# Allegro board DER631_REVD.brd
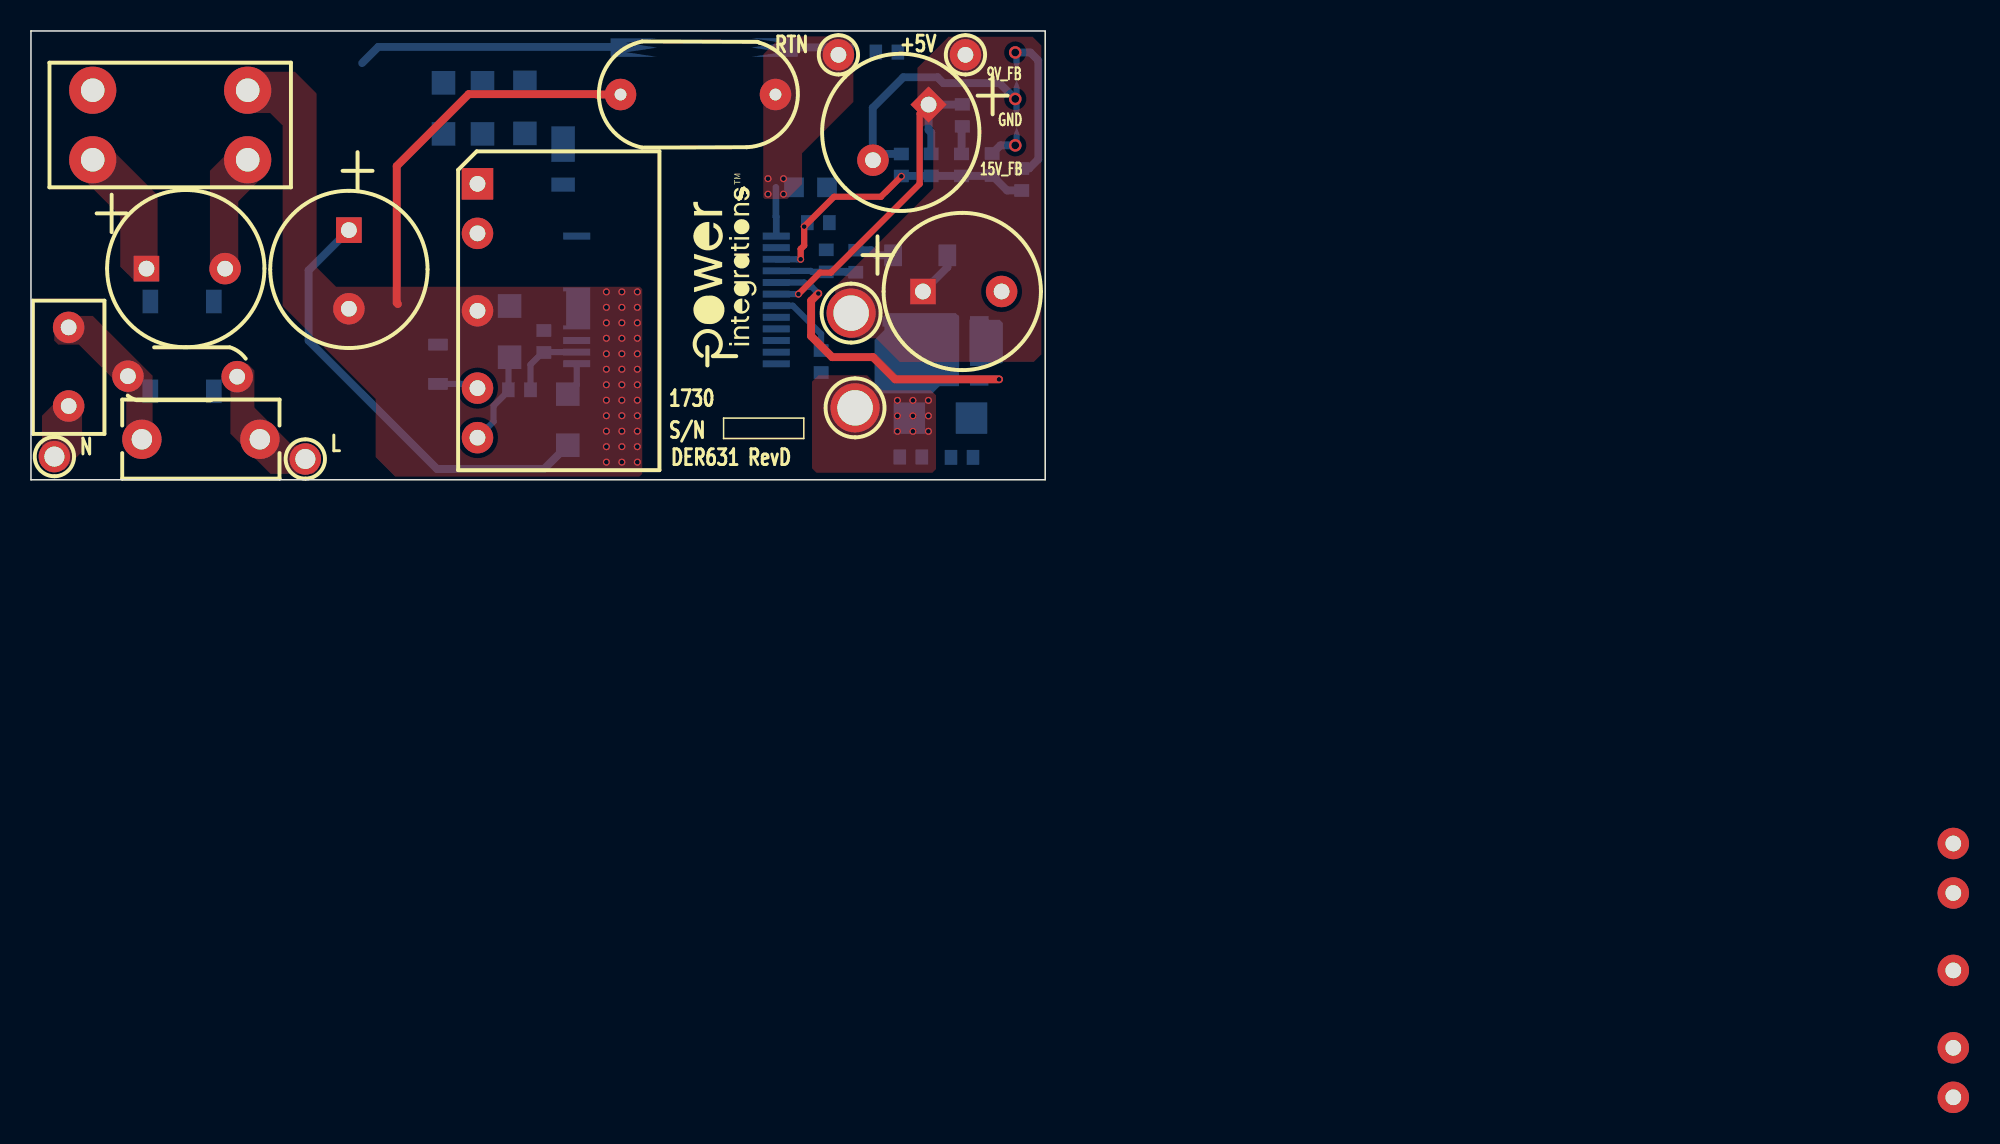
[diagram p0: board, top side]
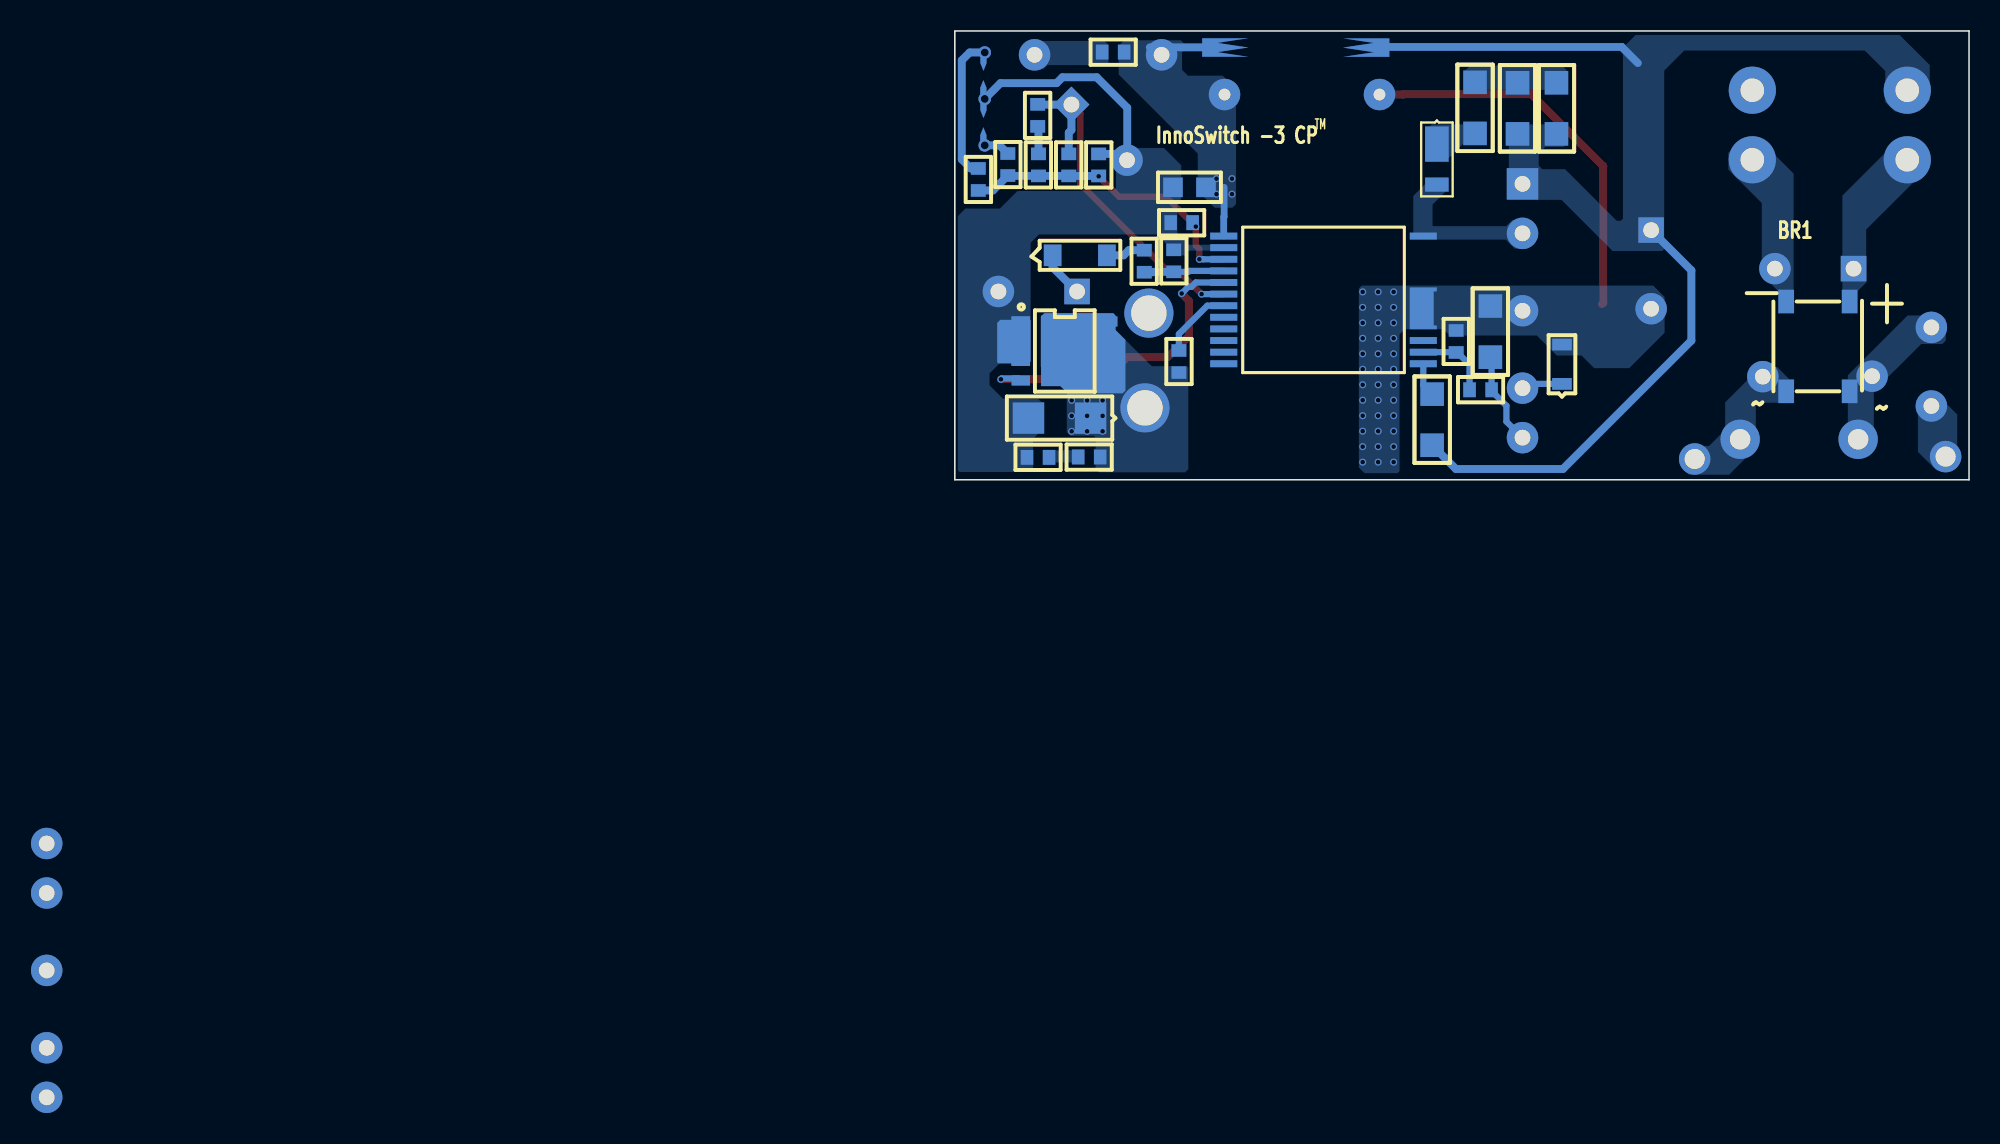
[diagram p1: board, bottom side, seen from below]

Outline 65.5 x 29 mm; copper layers: TOP, BOTTOM. Coordinates in mm from the lower left corner of the outline.
Outline path: 0,29 65.5,29 65.5,0 0,0 0,29

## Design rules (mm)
constraint set DEFAULT: min track width 0.508

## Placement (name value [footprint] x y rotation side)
BR1  Z4GP206L  [PI_SM_D_Z4]  7.72 11.53 180 bottom
C1  47 nF  [PI_NP395X200LS300D040]  14.78 2.62 180 top
C3  27 uF  [PIPOLCAPCYLD400LS200040]  20.53 16.13 270 top
C5  0.47 uF  [PISMC0603]  33.12 8.23 90 bottom
C6  22 uf  [PISMC1206]  30.91 7.92 90 bottom
C7  2.2 nF  [PINPCAPRAD374X275LS394D030]  38.07 24.89 0 top
C8  470 pF  [PISMC0603]  59.41 1.45 0 bottom
C9  2.2 uF  [PISMC0603]  51.36 13.44 90 bottom
C11  330 pF  [PISMC0603]  51.56 16.61 180 bottom
C12  4.7 nF  [PISMC0603]  60.1 21.06 270 bottom
C13  1 uF  [PISMC0603]  55.98 27.64 180 bottom
C14  560 uF  [PIPOLCAPCYLD400LS200040]  57.97 24.24 225 top
C15  560 uF  [PIPOLCAPCYLD400LS200040]  57.6 12.17 0 top
C17  27 uF  [PIPOLCAPCYLD400LS200040]  7.46 13.64 0 top
C18  470 pF  [PISMC1206]  26.64 22.35 90 bottom
D1  DFLR1600  [PISMDDFLR120012]  34.37 21.71 90 bottom
D2  BAV21WS-7-F  [PISMSOD323]  26.29 6.2 90 bottom
D4  STPS2H100AY  [PISMDSMA]  56.73 3.99 0 bottom
F1  1 A  [PI_RST_MICROFUSE]  2.43 4.77 90 top
FL1  Hole_90  [PI_HOLE_70MIL]  52.97 10.74 0 top
FL2  Hole_90  [PI_HOLE_70MIL]  53.22 4.62 0 top
L1  10 mH  [PI_IND_4P_590X295LS394X177D060]  13.97 20.7 0 top
NOREF  -  []  42.98 7.34 90 top
NOREF#2  -  []  0 29 0 top
NOREF#3  -  []  65.5 0 90 top
NOREF#4  -  []  -150.78 54.23 0 top
NOREF#5  -  []  -228.6 -144.78 0 top
Q3  BSC028N06LS3GATMA1  [PI_SM_PG-TDSON-8]  61.24 10.23 270 bottom
R5  51  [PISMR1206]  31.9 25.68 270 bottom
R8  10 k  [PISMR0603]  30.83 5.82 0 bottom
R10  47  [PISMR0603]  51.03 6.93 90 bottom
R13  4.7  [PISMR0603]  57.53 1.47 180 bottom
R14  100 k  [PISMR0603]  58.14 21.06 270 bottom
R15  33 K  [PISMR0603]  56.21 19.63 90 bottom
R16  0.005  [PISMR0805]  51.41 18.9 180 bottom
R19  2.2M  [PISMR1206]  34.67 2.23 90 bottom
R21  200 k  [PISMR1206]  29.16 22.35 90 bottom
R22  32.4 k  [PISMR0603]  63.98 18.69 90 bottom
R23  12.4 k  [PISMR0603]  62.08 19.66 90 bottom
R24  0.0  [PISMR0603]  60.15 24.26 270 bottom
R25  1 k  [PISMR0603]  53.26 14.83 270 bottom
RV1  275 Vac  [PIDISC350X160LS210X140040]  13.32 6.66 210 top
T2  EQ20  [PI_BOBBIN_EQ20_10P_H]  34.09 10.92 0 top
TP1  L  [PITPKEYSTONE100X100]  17.72 1.34 0 top
TP2  N  [PITPKEYSTONE100X100]  1.51 1.5 0 top
TP10  RET  [PITPKEYSTONE100X100]  52.15 27.46 0 top
TP11  +5V  [PITPKEYSTONE100X100]  60.35 27.46 0 top
U1  INN3268C  [PI_IC_INSOP_24D]  48.13 15.75 180 bottom
VR1  MMSZ5245B  [PI_SM_SOD-123_12]  59.18 14.5 180 bottom

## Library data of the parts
BR1 = DISCRETE BRIDGE_+~~-
C1 C5-C9 C11-C13 C18 = CAP NP
C3 C17 = CAP POL: alternate symbols: (pipolcapclyd400x675ls200040h)
C14 C15 = CAP POL
D1 D2 = DIODE
D4 = DIODE SCHOTTKY
F1 = FUSE: alternate symbols: (pirstmicrofusehoz)
FL1 FL2 = FlyingLead
L1 = INDUCTOR_4P_revD
Q3 = FET_N_TSDSON-8
R5 R8 R10 R13-R16 R19 R21-R25 = R
RV1 = VARISTOR: alternate symbols: (pi_disc_354x220_ls220x10_040_h)
T2 = BEQ20_10P
TP1 TP2 TP10 TP11 = TESTPOINT
U1 = DEV_InSOP_0
VR1 = DIODE_ZENER

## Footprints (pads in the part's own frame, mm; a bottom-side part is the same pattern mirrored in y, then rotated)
PI_BOBBIN_EQ20_10P_H
  rect 2.032x2.032 hole 1.016: 1(-5.25,8.2)
  round 2.032 hole 1.016: 2(-5.25,5) 3(-5.25,0) 4(-5.25,-5) 5(-5.25,-8.2) 6(90.061,-50.821) 7(90.061,-47.621) 8(90.061,-42.621) 9(90.061,-37.621) 10(90.061,-34.421)
PI_HOLE_70MIL
  round 3.175 hole 2.286: 1(0,0.025)
PI_IC_INSOP_24D
  rect 1.75x0.45 smd: 1(0,0) 2(0,-0.75) 3(0,-1.5) 4(0,-2.25) 5(0,-3) 6(0,-3.75) 7(0,-4.5) 8(0,-5.25) 9(0,-6) 10(0,-6.75) 11(0,-7.5) 12(0,-8.25) 13(12.89,-8.25) 14(12.89,-7.5) 15(12.89,-6.75) 24(12.89,0)
  custom 0.438x0.438 smd: 16(12.89,-4.67)
PI_IND_4P_590X295LS394X177D060
  round 3.048 hole 1.524: 1(0.025,-0.025) 2(0.025,4.47) 3(-9.982,4.47) 4(-9.982,-0.025)
PI_NP395X200LS300D040
  round 2.54 hole 1.321: 1(0,0) 2(7.62,0)
PI_RST_MICROFUSE
  round 2.032 hole 1.016: 1(0,0) 2(5.08,0)
PI_SM_D_Z4
  rect 1.016x1.524 smd: 1(0.01,-0.01) 2(0.01,-5.81) 3(-4.09,-5.81) 4(-4.09,-0.01)
PI_SM_PG-TDSON-8
  rect 0.66x1.194 smd: 1(0,0) 2(1.27,0) 3(2.54,0) 4(3.81,0) 5(3.81,5.65) 6(2.54,5.65) 7(1.27,5.65) 8(0,5.65)
PI_SM_SOD-123_12
  rect 1.143x1.397 smd: 1(0,0) 2(3.505,0)
PIDISC350X160LS210X140040
  round 2.032 hole 1.016: 1(0,0) 2(6.096,-3.556)
PINPCAPRAD374X275LS394D030
  round 2.032 hole 0.762: 1(0,0) 2(10.008,0)
PIPOLCAPCYLD400LS200040
  rect 1.651x1.651 hole 1.016: 1(0,0)
  round 2.032 hole 1.016: 2(5.08,0)
PISMC0603
  rect 0.813x0.965 smd: 1(0,0) 2(1.422,0)
PISMC1206
  rect 1.524x1.524 smd: 1(0,0) 2(3.302,0)
PISMDDFLR120012
  rect 2.286x1.524 smd: 1(-0.025,0)
  rect 0.914x1.524 smd: 2(-2.642,0)
PISMDSMA
  rect 2.032x2.032 smd: 1(0,0) 2(4.013,0)
PISMR0603
  rect 0.813x0.965 smd: 1(0,0) 2(1.422,0)
PISMR0805
  rect 1.27x1.27 smd: 1(0,0) 2(2.134,0)
PISMR1206
  rect 1.524x1.524 smd: 1(0,0) 2(3.302,0)
PISMSOD323
  rect 0.762x1.27 smd: 1(0,0) 2(2.54,0)
PITPKEYSTONE100X100
  round 2.032 hole 1.295: 1(0,0)

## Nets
GND_POWER: C8.2 C9.2 C11.1 C14.2 C15.2 D4.2 Q3.1(S1) R15.2 R16.1 U1.2
GND_SIGNAL: C3.2 C5.2 C6.2 C7.1 D2.2 L1.2 T2.3 U1.16
D6: Q3.6
D7: Q3.7
D8: Q3.8
NC8: U1.8
NC9: U1.9
NC10: U1.10
NC11: U1.11
NC12: U1.12
NC15: U1.15
S2: Q3.2
S3: Q3.3
N11018979: C13.1 C14.1 C15.1 FL1.1 R14.1 R24.1 TP11.1 U1.6 VR1.1
N11018987: C7.2 C13.2 R16.2 TP10.1 U1.1
N11019023: R10.2 U1.7
N11019027: D4.1 FL2.1 Q3.5 R10.1 R13.2
N11019129: Q3.4 U1.5
N11019153: D1.1 R5.2
N11019263: BR1.4 C17.2 L1.1
N11019293: C5.1 R8.2 U1.14
N11019397: BR1.3(AC2) C1.1 RV1.1 TP1.1
N11019401: C8.1 R13.1
N11019569: C6.1 R8.1 T2.5
N11019593: R19.2 U1.13(VPIN)
N11019613: C3.1 C18.1 L1.3 R19.1 R21.1 T2.1
N11019673: BR1.2 C1.2 F1.2 RV1.2
N11019681: BR1.1 C17.1 L1.4
N11019743: C11.2 C12.2 R14.2 R15.1 R22.1 R23.1 U1.3
N11020702: C18.2 R5.1 R21.2
N11020753: D1.2 T2.2 U1.24
N11026403: F1.1 TP2.1
N11053934: D2.1 T2.4
N11096846: R22.2
N11102317: R23.2
N11111738: C12.1 R24.2
N11113310: C9.1 R25.2 U1.4
N11114484: R25.1 VR1.2

Pads without a net: T2 6 7 8 9 10

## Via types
v1: diameter 0.813, hole 0.508, TOP to BOTTOM, 3 vias
v2: diameter 0.457, hole 0.305, TOP to BOTTOM, 55 vias

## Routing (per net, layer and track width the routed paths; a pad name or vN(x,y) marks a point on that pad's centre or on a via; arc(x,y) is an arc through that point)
GND_POWER: length 16
  BOTTOM w0.508: v1(63.57,24.61) 62.55,25.63 58.93,25.63 58.55,26.01 56.34,26.01 54.37,24.04 54.37,20.64 54.78,21.05 R15.2
GND_SIGNAL: length 25.3
  TOP w0.508: 23.7,11.35 23.62,11.43 23.62,20.27 28.27,24.92 36.53,24.92 36.55,24.89 C7.1
  vias: v2(37.16,12.14) v2(37.16,11.14) v2(37.16,10.14) v2(37.16,9.14) v2(37.16,8.14) v2(37.16,7.14) v2(37.16,6.14) v2(37.16,5.14) v2(37.16,4.14) v2(37.16,3.14) v2(37.16,2.14) v2(37.16,1.14) v2(38.16,12.14) v2(38.16,11.14) v2(38.16,10.14) v2(38.16,9.14) v2(38.16,8.14) v2(38.16,7.14) v2(38.16,6.14) v2(38.16,5.14) v2(38.16,4.14) v2(38.16,3.14) v2(38.16,2.14) v2(38.16,1.14) v2(39.16,12.14) v2(39.16,11.14) v2(39.16,10.14) v2(39.16,9.14) v2(39.16,8.14) v2(39.16,7.14) v2(39.16,6.14) v2(39.16,5.14) v2(39.16,4.14) v2(39.16,3.14) v2(39.16,2.14) v2(39.16,1.14)
N11018979: length 26
  TOP w0.4: C14.1 57.39,23.67 57.39,19.11 51.66,13.39 50.95,13.39 v2(49.56,12)
  BOTTOM w0.4: U1.6 v2(49.56,12)
  BOTTOM w0.508: R24.1 60.13,24.24 C14.1 57.97,22.6 58.14,22.43 R14.1 ; C15.1 57.62,12.17 59.18,13.73 VR1.1
N11018987: length 7.1
  BOTTOM w0.432: U1.1 48.13,16.98 48.11,17 48.11,18.9
  BOTTOM w0.508: 49,27.94 52.91,27.94
  vias: v2(47.6,19.46) v2(47.6,18.46) v2(48.6,19.46) v2(48.6,18.46)
N11019023: length 4.7
  BOTTOM w0.4: U1.7 49.2,11.25 51.03,9.42 R10.2
N11019027:
  vias: v2(55.96,5.13) v2(55.96,4.13) v2(55.96,3.13) v2(56.96,5.13) v2(56.96,4.13) v2(56.96,3.13) v2(57.96,5.13) v2(57.96,4.13) v2(57.96,3.13)
N11019129: length 20.6
  TOP w0.508: v2(62.52,6.49) 55.82,6.49 54.38,7.92 51.74,7.92 50.38,9.28 50.38,11.57 v2(50.85,12.04)
  BOTTOM w0.4: v2(50.85,12.04) 50.42,12.47 50.22,12.47 49.94,12.75 U1.5 ; Q3.4 61.37,6.55 62.47,6.55 v2(62.52,6.49)
N11019293: length 4.9
  BOTTOM w0.4: U1.14 33.14,8.25 C5.1 33.05,8.23 32.26,7.44 R8.2
N11019569: length 6.1
  BOTTOM w0.4: C6.1 30.83,7.84 R8.1 30.83,5.74 29.88,4.78 29.88,3.76 T2.5
N11019593: length 2.2
  BOTTOM w0.4: U1.13 35.24,6.11 R19.2
N11019613: length 45.7
  BOTTOM w0.508: 21.39,26.92 22.43,27.97 37.59,27.97 37.62,27.94 ; R19.1 33.14,0.7 26.23,0.7 17.93,8.99 17.93,13.53 C3.1
N11019743: length 19.6
  TOP w0.4: v2(56.21,19.61) 54.89,18.29 51.86,18.29 v2(49.94,16.36) 49.94,15.14 49.71,14.91 v2(49.71,14.25)
  BOTTOM w0.4: v2(49.71,14.25) 49.45,14.25 49.45,14.25 U1.3
  BOTTOM w0.508: R22.1 63.04,18.69 R23.1 62.06,19.64 C12.2 R14.2 58.14,19.63 R15.1
N11053934: length 2.7
  BOTTOM w0.4: D2.1 28.56,6.2 T2.4
N11096846: length 9.4
  BOTTOM w0.508: R22.2 64.47,20.12 65.05,20.7 65.05,27.1 64.54,27.61 v1(63.57,27.61)
N11102317: length 1.7
  BOTTOM w0.508: R23.2 62.61,21.61 v1(63.57,21.61)
N11111738: length 1.8
  BOTTOM w0.508: C12.1 60.1,22.78 R24.2
N11113310: length 5.2
  BOTTOM w0.4: U1.4 50.36,13.5 50.42,13.44 C9.1
  BOTTOM w0.508: R25.2 52.7,13.41 52.68,13.44 C9.1
N11114484: length 2.5
  BOTTOM w0.508: VR1.2 54.6,14.5 54.27,14.83 R25.1

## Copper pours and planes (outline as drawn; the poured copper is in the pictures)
GND_POWER on BOTTOM (solid shape): 62.76,10.13 62.76,7.59 62.69,7.52 60.73,7.52 60.6,7.65 60.6,10.34 62.56,10.34
GND_POWER on BOTTOM (solid shape): 61.84,8.63 61.84,8.63 61.84,7.36 60.64,7.36 60.64,10.56 61.84,10.56
GND_POWER on BOTTOM: 62.4,5.25 63.26,6.11 63.26,6.87 62.59,7.54 62.41,7.54 62.41,10.01 62.33,10.08 60.63,10.08 60.6,10.11 60.6,15.32 60.07,15.85 52.45,15.85 51.82,15.21 51.82,14.67 51.64,14.5 50.64,14.5 50.33,14.81 47.37,14.81 47.29,14.88 47.29,15.14 47.35,15.19 50.37,15.19 51.13,15.95 51.13,17.91 50.88,18.16 50.88,20.32 51.99,21.44 54.74,21.44 55.09,21.08 55.09,18.87 55.31,18.66 61.46,18.66 62.59,17.53 64.82,17.53 65.3,17.04 65.3,0.61 65.2,0.51 60.66,0.51 60.45,0.71 60.45,2.64 59.87,3.23 59.87,4.98 60.13,5.25
GND_SIGNAL on TOP: 39.32,12.47 39.47,12.32 39.47,0.38 39.29,0.2 23.52,0.2 22.26,1.46 22.26,5.22 16.26,11.23 16.26,22.89 15.44,23.7 13.74,23.7 12.9,24.54 12.9,25.83 13.44,26.37 17.04,26.37 18.44,24.97 18.44,13.74 19.71,12.47
GND_SIGNAL on BOTTOM: 36.45,9.73 33.93,9.73 33.53,9.32 27.91,9.32 26.62,8.03 25.02,8.03 24.21,7.21 21.95,7.21 19.66,9.5 19.66,11.81 20.4,12.55 39.22,12.55 39.41,12.36 39.41,0.8 39.04,0.43 36.91,0.43 36.78,0.56 36.78,9.4
D8 on BOTTOM (solid shape): 59.93,6.05 55.54,6.05 55.54,10.61 59.93,10.61
N11018979 on TOP: 51.94,12.5 58.27,18.82 58.27,22.73 58.04,22.96 57.76,22.96 57.51,22.71 57.38,22.71 57.25,22.83 57.25,26.62 59.26,28.63 64.69,28.63 65.25,28.07 65.25,8.1 64.77,7.62 56.11,7.62 54.58,9.14 52.86,9.14 51.94,10.06
N11018979 on BOTTOM: 60.66,28.35 55.83,28.35 55.58,28.09 55.58,26.95 55.73,26.8 59.51,26.8 59.78,26.53 60.78,26.53 61.21,26.96 61.21,27.79
N11018987 on BOTTOM (solid shape): 49.53,27.33 46.53,27.33 48.53,27.63 46.53,27.93 48.53,28.23 46.53,28.53 49.53,28.53
N11018987 on TOP: 52.6,28.65 48.46,28.65 47.29,27.48 47.29,18.24 47.4,18.14 48.84,18.14 49.8,19.09 49.8,21.09 53.11,24.41 53.11,28.14
N11018987 on BOTTOM: 47.35,17.81 47.35,25.25 48.21,26.11 50.44,26.11 50.83,26.49 50.83,27.64 50.65,27.81 50.65,28.14 50.9,28.4 54.56,28.4 54.91,28.04 54.91,26.19 49.81,21.08 49.81,18.67 48.74,17.6 48.74,17.58 47.57,17.58
N11019027 on BOTTOM (solid shape): 59.94,10.54 59.94,7.32 58.27,5.64 58.27,5.59 54.66,5.59 54.48,5.77 54.48,9.04 55.12,9.68 55.12,10.62 55.27,10.77 59.72,10.77
N11019027 on TOP: 58.14,5.77 54.99,5.77 54,6.76 50.85,6.76 50.44,6.35 50.44,0.74 50.72,0.46 58.22,0.46 58.45,0.69 58.45,5.46
N11019027 on BOTTOM: 54.76,9.32 52.78,7.34 50.52,7.34 50.42,7.24 50.42,0.69 50.62,0.48 56.16,0.48 56.41,0.74 56.41,2.74 56.52,2.84 58.04,2.84 58.27,3.07 58.27,5.79 54.81,5.79 54.76,5.84
N11019153 on BOTTOM: 31.39,22.96 34.7,22.96 34.9,22.76 34.9,20.85 34.77,20.73 33.66,20.73 32.64,21.74 31.32,21.74 31.22,21.84 31.22,22.78
N11019263 on TOP: 13.39,21.79 14.94,21.79 15.24,21.49 15.24,19.84 13.39,17.98 13.39,13.26 13.03,12.9 11.99,12.9 11.56,13.34 11.56,19.96
N11019263 on BOTTOM: 11.33,19.79 13.26,21.72 14.96,21.72 15.54,21.13 15.54,20.04 13.39,17.88 13.39,13.26 12.27,12.14 12.27,10.92 12.22,10.87 11.48,10.87 11.33,11.02
N11019397 on TOP: 12.88,7.21 12.88,2.97 15.47,0.38 18.24,0.38 18.52,0.66 18.52,1.83 18.11,2.24 16.87,2.24 14.43,4.67 14.43,7.06 14.02,7.47 13.13,7.47
N11019397 on BOTTOM: 11.56,6.45 12.4,7.29 13.46,7.29 15.75,5 15.75,3.23 16.79,2.18 18.06,2.18 18.59,1.65 18.59,0.81 18.11,0.33 15.49,0.33 13.77,2.06 13.77,4.78 13.56,4.98 11.73,4.98 11.56,5.16
N11019401 on BOTTOM: 59.8,1.79 59.8,1.23 59.69,1.12 57.35,1.12 57.2,1.27 57.2,1.75 57.35,1.91 59.69,1.91
N11019613 on BOTTOM (solid shape): 38.43,28.22 40.43,27.92 38.43,27.62 40.43,27.32 37.43,27.32 37.43,28.52 40.43,28.52
N11019613 on BOTTOM: 19.68,26.44 19.68,14.91 19.81,14.78 23.01,14.78 26.31,18.08 29.51,18.08 29.72,18.29 29.72,22.81 29.57,22.96 26.19,22.96 26.04,22.81 26.04,21.64 26.16,21.51 27.36,21.51 27.79,21.08 27.79,20.29 27.56,20.07 26.09,20.07 22.76,16.74 22.48,16.74 22.35,16.87 22.35,27.91 21.53,28.74 4.48,28.74 2.54,26.8 2.54,24.51 3.25,23.8 4.8,23.8 5.44,24.43 5.44,24.87 5.41,24.89 5.41,26.42 6.73,27.74 18.39,27.74
N11019673 on TOP: 1.73,10.59 1.5,10.36 1.5,8.99 1.75,8.74 3.1,8.74 6.15,5.69 6.15,1.88 6.45,1.57 7.47,1.57 7.85,1.96 7.85,6.73 3.99,10.59
N11019673 on BOTTOM: 7.82,1.96 7.82,6.76 3.96,10.62 1.75,10.62 1.5,10.36 1.5,8.99 1.71,8.78 3.09,8.78 6.15,5.71 6.15,1.93 6.48,1.6 7.47,1.6
N11019681 on TOP: 5.77,17.04 2.84,19.96 2.84,21.36 3.17,21.69 4.88,21.69 8.18,18.39 8.18,13.08 7.92,12.83 6.71,12.83 5.77,13.77
N11019681 on BOTTOM: 2.74,20.07 2.74,21.18 3.23,21.67 4.88,21.67 8.18,18.36 8.18,11.13 8,10.95 7.29,10.95 7.29,12.09 6.64,12.74 6.64,16.17
N11020702 on BOTTOM: 25.98,26.47 25.98,25.5 26.29,25.2 32.26,25.2 32.54,25.48 32.54,26.44 32.23,26.75 26.26,26.75
N11020753 on BOTTOM: 33.78,19.33 33.78,18.64 34.65,17.78 34.65,16.43 34.59,16.38 29.9,16.38 29.49,16.79 28.45,16.79 28.07,16.41 28.07,15.52 28.65,14.94 29.34,14.94 29.92,15.52 35.89,15.52 35.89,18.34 34.9,19.33
N11026403 on TOP: 0.71,1.12 0.71,4.14 1.88,5.31 3.05,5.31 3.3,5.05 3.3,1.8 2.18,0.69 2.18,0.64 1.19,0.64
N11026403 on BOTTOM: 3,5.31 1.85,5.31 0.76,4.22 0.76,1.09 1.24,0.61 2.11,0.61 3.3,1.8 3.3,5

Small or netless copper shapes (teardrops, artwork), in the pictures only: 4 on BOTTOM

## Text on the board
Ref Des/Silkscreen Bottom: TM | InnoSwitch -3 CP
User.Comments: 10 | 13 | /16 | 25 | 20 | NG | 7
Ref Des/Silkscreen Top: 15V_FB | 9V_FB | GND | N | L | 1730 | S/N | DER631 RevD | RTN | +5V
DEVICE_TYPE_BOTTOM: 14.  FAB HOUSE LOGO,DATE CODE TO BE IN SILK SCREEN ONLY.DO NOT USE COPPER. | 13.  MATERIAL FR4 COPPER 2oz THICKNESS 0.062"
User.5: FIGURE | FINISHED_SIZE | 12.0 | 20.0 | 30.0 | 40.0 | 51.0 | 52.0 | 60.0 | 90.0 | DRILL CHART: TOP to BOTTOM | ALL UNITS ARE IN MILS | PLATED | QTY | 55 | 3 | 2 | 24 | 4
